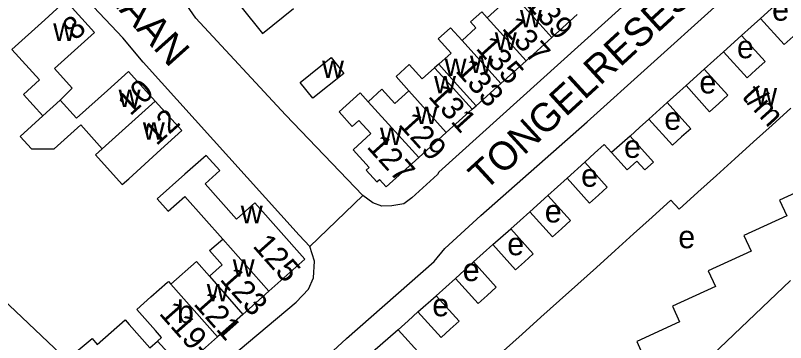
# Model space of a CAD drawing. Extents: x 161775 to 163181, y 382878 to 383925.
# Drawn here: x 162592 to 162727.8, y 383505.2 to 383562.8 of the extents above; entities that cross this region are included whole.
import ezdxf

# ---------------------------------------------------------------- set-up
doc = ezdxf.new("R2010")
doc.units = 0
for name, color, linetype in [('BLT_Basislijn', 7, 'Continuous'), ('BLT_Bebouwing', 7, 'Continuous'), ('BLT_Centroide', 7, 'Continuous'), ('BLT_Huisnummer', 7, 'Continuous'), ('BLT_Huisnummer_ tussenligend', 7, 'Continuous'), ('BLT_Huisnummer_reeks', 7, 'Continuous'), ('BLT_Onderdoorgang_en_onderverdeling', 7, 'Continuous'), ('BLT_Onderverdeling_panden', 7, 'Continuous'), ('BLT_Straatnaam', 7, 'Continuous'), ('BLT_Vlakafsluiter', 7, 'Continuous')]:
    doc.layers.add(name, color=color, linetype=linetype)

msp = doc.modelspace()

# ---------------------------------------------------------------- linework, layer by layer
at = {"layer": 'BLT_Basislijn'}
for p, q in [((162726.56, 383565.18), (162723.38, 383562.3)), ((162720.02, 383559.27), (162716.83, 383556.43)), ((162713.45, 383553.38), (162710.24, 383550.48)), ((162706.9, 383547.46), (162703.69, 383544.55)), ((162700.38, 383541.56), (162697.1, 383538.64)), ((162689.26, 383534.15), (162692.37, 383536.98)), ((162682.68, 383528.19), (162685.88, 383531.1)), ((162676.15, 383522.45), (162679.35, 383525.18)), ((162669.57, 383516.48), (162672.74, 383519.37)), ((162662.96, 383510.56), (162666.18, 383513.42)), ((162659.49, 383507.42), (162653.62, 383502.31))]:
    msp.add_line(p, q, dxfattribs=at)
for points in [[(162643.92, 383522.1), (162642.03, 383524.09), (162614.49, 383554.61), (162610.89, 383558.85), (162602.61, 383567.68), (162600, 383570.89), (162597.46, 383574.02)], [(162623.8, 383562.33), (162622.18, 383564.66), (162621.83, 383565.9), (162621.83, 383568.86), (162622.55, 383570.67), (162623.65, 383571.96), (162624.32, 383572.31), (162626.44, 383574.02)], [(162631.01, 383482.55), (162628.85, 383484.67), (162628.29, 383485.46), (162650.35, 383505.87), (162665.82, 383519.46), (162667.7, 383521.72), (162674.07, 383527.56), (162692.83, 383544.06), (162715.29, 383564.27), (162716.81, 383565.45), (162725.94, 383574.02)], [(162709.65, 383574.02), (162666.66, 383535.19), (162666.44, 383534.79), (162661.91, 383530.65), (162660.47, 383529.64), (162658.37, 383529.25), (162656.59, 383529.18), (162655, 383529.77), (162653.22, 383531.07)], [(162653.22, 383531.07), (162639.59, 383545.32), (162623.8, 383562.33)], [(162734.3, 383533.71), (162726.74, 383530.24), (162728, 383527.48), (162720.44, 383524.01), (162721.71, 383521.25), (162714.14, 383517.78), (162715.41, 383515.02), (162707.85, 383511.55), (162709.11, 383508.79), (162701.55, 383505.32), (162702.82, 383502.56), (162695.25, 383499.09), (162696.54, 383496.28), (162688.8, 383492.9), (162690.02, 383490.1), (162681.72, 383486.48)], [(162515.26, 383407.9), (162516.28, 383406.99), (162517.56, 383406.64), (162519.98, 383407.22), (162520.74, 383408.09), (162522.92, 383409.68), (162549.37, 383433.01), (162589.33, 383467.77), (162592.9, 383470.8), (162593.79, 383471.34), (162600, 383476.66), (162604.65, 383480.65), (162607.41, 383483.28), (162627.95, 383500.95), (162641.5, 383512.26), (162643.67, 383514.55), (162644.53, 383516.57), (162644.72, 383519.48), (162643.92, 383522.1)], [(162581.68, 383520.39), (162600, 383503.11), (162600.97, 383502.13)], [(162728.69, 383516.08), (162713.68, 383501.84), (162688.53, 383479.69)]]:
    msp.add_lwpolyline(points, dxfattribs=at)
at = {"layer": 'BLT_Bebouwing'}
for p, q in [((162691.06, 383562.98), (162686.6, 383558.96)), ((162723.38, 383562.3), (162721.7, 383560.79)), ((162721.7, 383560.79), (162720.02, 383559.27)), ((162686.6, 383558.96), (162682.02, 383554.83)), ((162716.83, 383556.43), (162715.14, 383554.9)), ((162682.02, 383554.83), (162677.59, 383550.83)), ((162715.14, 383554.9), (162713.45, 383553.38)), ((162666.63, 383554.22), (162665.89, 383553.61)), ((162677.59, 383550.83), (162673.23, 383546.9)), ((162710.24, 383550.48), (162708.57, 383548.97)), ((162708.57, 383548.97), (162706.9, 383547.46)), ((162672.5, 383546.28), (162673.23, 383546.9)), ((162672.5, 383546.28), (162667.94, 383542.17)), ((162725.45, 383543.49), (162728.72, 383546.45)), ((162703.69, 383544.55), (162702.04, 383543.05)), ((162702.04, 383543.05), (162700.38, 383541.56)), ((162722.15, 383540.52), (162725.45, 383543.49)), ((162667.94, 383542.17), (162663.1, 383537.8)), ((162718.87, 383537.56), (162722.15, 383540.52)), ((162694.08, 383538.53), (162692.37, 383536.98)), ((162663.1, 383537.8), (162657.36, 383532.62)), ((162715.6, 383534.6), (162718.87, 383537.56)), ((162712.34, 383531.65), (162715.6, 383534.6)), ((162689.26, 383534.15), (162687.57, 383532.63)), ((162687.57, 383532.63), (162685.88, 383531.1)), ((162704.26, 383527.26), (162707.57, 383530.24)), ((162682.68, 383528.19), (162681.01, 383526.68)), ((162681.01, 383526.68), (162679.35, 383525.18)), ((162700.98, 383524.31), (162704.26, 383527.26)), ((162697.73, 383521.38), (162700.98, 383524.31)), ((162676.15, 383522.45), (162674.45, 383520.91)), ((162674.45, 383520.91), (162672.74, 383519.37)), ((162694.43, 383518.41), (162697.73, 383521.38)), ((162691.15, 383515.46), (162694.43, 383518.41)), ((162669.57, 383516.48), (162667.87, 383514.95)), ((162687.92, 383512.55), (162691.15, 383515.46)), ((162636.67, 383514.22), (162632.06, 383510.13)), ((162667.87, 383514.95), (162666.18, 383513.42)), ((162684.65, 383509.61), (162687.92, 383512.55)), ((162632.06, 383510.13), (162627.6, 383506.18)), ((162662.96, 383510.56), (162661.22, 383508.99)), ((162661.22, 383508.99), (162659.49, 383507.42)), ((162681.35, 383506.64), (162684.65, 383509.61)), ((162627.6, 383506.18), (162622.03, 383501.24)), ((162678.06, 383503.68), (162681.35, 383506.64))]:
    msp.add_line(p, q, dxfattribs=at)
for points in [[(162633.15, 383573.9), (162627.66, 383569.52), (162635.52, 383559.67), (162641.01, 383564.05)], [(162679.76, 383566.55), (162678.67, 383567.64), (162676.59, 383565.76), (162677.62, 383564.62), (162675.18, 383562.42)], [(162597.18, 383562.08), (162600, 383564.62), (162600.89, 383565.43), (162605.93, 383559.84), (162598.84, 383553.46), (162601.96, 383550), (162599.87, 383547.88)], [(162675.18, 383562.42), (162674.22, 383563.48), (162672.22, 383561.68), (162673.18, 383560.62), (162670.74, 383558.42)], [(162596.8, 383545.1), (162593.38, 383548.9), (162596.21, 383551.45), (162591.36, 383556.83), (162597.18, 383562.08)], [(162729.13, 383559.13), (162727.54, 383557.69), (162723.38, 383562.3)], [(162666.63, 383554.22), (162668.8, 383556.18), (162666.53, 383558.69), (162668.72, 383560.66), (162670.74, 383558.42)], [(162720.02, 383559.27), (162724.17, 383554.68), (162722.58, 383553.25)], [(162722.58, 383553.25), (162721, 383551.81), (162716.83, 383556.43)], [(162647.68, 383555.4), (162649.91, 383552.61), (162644.43, 383548.24), (162642.21, 383551.03), (162647.68, 383555.4)], [(162665.89, 383553.61), (162663.71, 383551.64), (162661.44, 383554.16), (162659.11, 383552.05), (162661.36, 383549.52)], [(162713.45, 383553.38), (162717.62, 383548.76), (162716.02, 383547.31)], [(162616.63, 383547.74), (162611.93, 383552.96), (162608.21, 383549.62), (162602.76, 383544.69), (162599.87, 383547.88)], [(162661.36, 383549.52), (162658.87, 383547.29), (162656.61, 383549.8), (162654.2, 383547.62)], [(162716.02, 383547.31), (162714.41, 383545.86), (162710.24, 383550.48)], [(162654.2, 383547.62), (162652.79, 383549.18), (162649.08, 383545.83), (162651.39, 383543.27), (162652.56, 383544.33), (162654.67, 383541.99), (162651.53, 383539.15), (162654.37, 383536.01), (162653.85, 383535.54), (162655.72, 383533.47), (162656.2, 383533.91), (162657.36, 383532.62)], [(162607.27, 383539.31), (162606.1, 383538.25), (162610.81, 383533.02), (162611.95, 383534.05), (162617.62, 383539.18), (162621.34, 383542.52), (162616.63, 383547.74)], [(162706.9, 383547.46), (162711.06, 383542.85), (162709.46, 383541.4)], [(162596.8, 383545.1), (162592.83, 383541.51), (162594.8, 383539.33), (162598.79, 383539.32), (162603.5, 383543.56), (162607.27, 383539.31)], [(162709.46, 383541.4), (162707.85, 383539.95), (162703.69, 383544.55)], [(162700.38, 383541.56), (162704.52, 383536.98), (162702.96, 383535.58)], [(162697.1, 383538.64), (162695.8, 383540.08), (162694.08, 383538.53)], [(162702.96, 383535.58), (162701.56, 383537.13), (162699.85, 383535.59), (162697.1, 383538.64)], [(162636.67, 383514.22), (162643.01, 383519.84), (162634.19, 383529.79), (162630.95, 383526.91), (162625.41, 383533.16), (162628.01, 383535.47), (162625.62, 383538.16), (162621.88, 383534.85), (162616.99, 383530.52), (162618.94, 383528.32), (162621.86, 383530.92), (162628.53, 383523.4)], [(162692.37, 383536.98), (162696.36, 383532.57), (162694.8, 383531.16)], [(162694.8, 383531.16), (162693.24, 383529.75), (162689.26, 383534.15)], [(162707.57, 383530.24), (162709.01, 383528.65), (162712.34, 383531.65)], [(162685.88, 383531.1), (162689.88, 383526.67), (162688.27, 383525.22)], [(162688.27, 383525.22), (162686.67, 383523.77), (162682.68, 383528.19)], [(162679.35, 383525.18), (162683.3, 383520.8), (162681.74, 383519.4)], [(162626.18, 383516.84), (162628.45, 383518.85), (162626.22, 383521.36), (162628.53, 383523.4)], [(162681.74, 383519.4), (162680.18, 383517.99), (162676.15, 383522.45)], [(162619.39, 383515.44), (162623.89, 383519.42), (162626.18, 383516.84)], [(162672.74, 383519.37), (162676.77, 383514.91), (162675.18, 383513.47)], [(162617.05, 383505.41), (162617.76, 383506.04), (162616.67, 383507.27), (162613.38, 383510.99), (162615.86, 383513.19), (162618.8, 383515.81), (162618.95, 383515.94), (162619.39, 383515.44)], [(162675.18, 383513.47), (162673.59, 383512.03), (162669.57, 383516.48)], [(162666.18, 383513.42), (162670.22, 383508.94), (162668.63, 383507.49)], [(162668.63, 383507.49), (162667.03, 383506.05), (162662.96, 383510.56)], [(162606.39, 383504.83), (162611.3, 383509.18), (162612.03, 383508.36), (162615.7, 383504.22), (162617.05, 383505.41)], [(162659.49, 383507.42), (162663.53, 383502.94), (162661.88, 383501.38), (162662.76, 383500.38), (162665.21, 383497.65), (162667.95, 383494.58)], [(162600.97, 383502.13), (162605.48, 383505.85), (162606.39, 383504.83)]]:
    msp.add_lwpolyline(points, dxfattribs=at)
at = {"layer": 'BLT_Onderdoorgang_en_onderverdeling'}
for points in [[(162672.5, 383546.28), (162669.15, 383549.99), (162665.89, 383553.61)], [(162673.23, 383546.9), (162669.88, 383550.62), (162666.63, 383554.22)]]:
    msp.add_lwpolyline(points, dxfattribs=at)
at = {"layer": 'BLT_Onderverdeling_panden'}
for p, q in [((162686.6, 383558.96), (162679.76, 383566.55)), ((162682.02, 383554.83), (162675.18, 383562.42)), ((162677.59, 383550.83), (162670.74, 383558.42)), ((162667.94, 383542.17), (162661.36, 383549.52)), ((162596.8, 383545.1), (162599.87, 383547.88)), ((162616.63, 383547.74), (162607.27, 383539.31)), ((162663.1, 383537.8), (162654.2, 383547.62)), ((162628.53, 383523.4), (162636.67, 383514.22)), ((162626.18, 383516.84), (162632.06, 383510.13)), ((162619.39, 383515.44), (162627.6, 383506.18)), ((162617.05, 383505.41), (162619.57, 383502.65))]:
    msp.add_line(p, q, dxfattribs=at)
at = {"layer": 'BLT_Vlakafsluiter'}
msp.add_line((162643.92, 383522.1), (162653.22, 383531.07), dxfattribs=at)

# ---------------------------------------------------------------- texts
at = {"layer": 'BLT_Centroide'}
for s, p in [('e', (162725.42, 383561.9)), ('w', (162680.95, 383560.73)), ('w', (162598.64, 383558.34)), ('w', (162676.52, 383556.75)), ('e', (162719.22, 383555.28)), ('w', (162646.05, 383551.81)), ('w', (162667.67, 383552.15)), ('w', (162672.14, 383552.66)), ('w', (162665.81, 383549.08)), ('e', (162712.6, 383549.08)), ('w', (162610.17, 383546.66)), ('w', (162722.43, 383546.95)), ('w', (162662.55, 383543.67)), ('e', (162706.4, 383542.66)), ('w', (162614.45, 383540.91)), ('w', (162656.27, 383539.97)), ('e', (162699.31, 383537.72)), ('e', (162691.74, 383532.63)), ('w', (162631.72, 383526.19)), ('e', (162685.33, 383526.33)), ('e', (162708.88, 383521.79)), ('e', (162678.71, 383520.55)), ('w', (162630.3, 383516.77)), ('e', (162670.86, 383516)), ('w', (162625.72, 383512.42)), ('b', (162620.48, 383508.58)), ('e', (162665.49, 383509.79))]:
    msp.add_text(s, height=4, dxfattribs=at).set_placement(p)
at = {"layer": 'BLT_Huisnummer'}
for s, rotation, p in [('139', 312.0406, (162681.75, 383564.88)), ('8', 42.0324, (162602.5, 383558.25)), ('133', 312.0381, (162669.45, 383552.99)), ('10', 42.0305, (162612.23, 383545)), ('131', 312.0381, (162664.64, 383548.48)), ('12', 42.0324, (162616.85, 383539.75)), ('127', 312.0468, (162653.8, 383539.59)), ('125', 311.5672, (162633.68, 383522.12)), ('119-a', 311.405, (162617.17, 383510.23))]:
    msp.add_text(s, height=4, rotation=rotation, dxfattribs=at).set_placement(p)
at = {"layer": 'BLT_Huisnummer_ tussenligend'}
for s, rotation, p in [('137', 312.0389, (162677.66, 383560.46)), ('135', 312.0389, (162673.03, 383556.97)), ('129', 312.0468, (162659.38, 383543.53)), ('123', 311.5689, (162627.88, 383516.24)), ('121', 311.5689, (162623.25, 383511.91))]:
    msp.add_text(s, height=4, rotation=rotation, dxfattribs=at).set_placement(p)
at = {"layer": 'BLT_Huisnummer_reeks'}
msp.add_text('t/m', height=4, rotation=312.0941, dxfattribs=at).set_placement((162719.93, 383548.42))
at = {"layer": 'BLT_Straatnaam'}
for s, height, rotation, p in [('PELIKAANLAAN', 4.9999, 311.9288, (162585.82, 383590.8)), ('TONGELRESESTRAAT', 5, 42.4828, (162674.77, 383531.77))]:
    msp.add_text(s, height=height, rotation=rotation, dxfattribs=at).set_placement(p)

doc.saveas('drawing.dxf')
